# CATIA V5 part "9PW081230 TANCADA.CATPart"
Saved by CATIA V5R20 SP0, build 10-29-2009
Part number: 9PW081230 TANCADA
Revision: ANY
Definition: UNKNOWN
Nomenclature: 9PW081230 TANCADA
Source: Unknown
Bounding box of the stored display mesh (mm): x -175 to 0, y -6.7 to 4.5, z -6.1 to 6.1
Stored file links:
  C:\Users\Utente\Desktop\IO LAVORO\3D X SITO CF\CUMSA\3D files PW\pw081230\pw081230_injection\9PW081230 TANCADA.CATPart
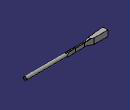
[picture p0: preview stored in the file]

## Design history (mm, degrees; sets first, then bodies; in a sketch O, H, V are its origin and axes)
Body1 "Chaflán4" (main body)
  Solid1: solid without history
